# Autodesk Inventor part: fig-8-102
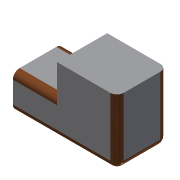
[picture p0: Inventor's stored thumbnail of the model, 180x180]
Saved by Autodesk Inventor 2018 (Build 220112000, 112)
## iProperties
Shininess: 64.0
Length Units: 11269
Angle Units: 11279
Time Units: 11290
Mass Units: 11283
Length Display Precision: 3
Angle Display Precision: 2
Compacted: True
Part Number: fig-8-102
Document SubType Name: Modeling
Created: 2002-12
Designer: deepak
Density: 1 g/cm^3
Material: Generic
Appearance: Default
Density: 0.0
Volumn: 0.0
Area: 0.0
PropertySet Name: Model Information
Control State: 0
Master: False
Checked Out: False
Author: deepak
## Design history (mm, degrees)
sketch "Sketch1"
  geometry: L1 (-26.972, 23.346)-(8.906, 23.346); L2 (8.906, 23.346)-(8.906, 5.025); L3 (8.906, -15.84)-(-26.972, -15.84); L4 (-26.972, -15.84)-(-26.972, 23.346); L5 (8.906, -15.84)-(35.369, -15.84); L6 (35.369, -15.84)-(35.369, 5.025); L7 (35.369, 5.025)-(8.906, 5.025)
  constraints: 14 end point, 3 parallel, 2 horizontal, 2 perpendicular
extrude "Extrusion1" new body sketch "Sketch1" stored distance "d0" = 30; taper "d1" = 0 deg
fillet "Fillet1" dims "d2" = 4, "d3" = 4
delete_face "Delete Face1"
delete_face "Delete Face2"
delete_face "Delete Face3"
body "Solid1"
